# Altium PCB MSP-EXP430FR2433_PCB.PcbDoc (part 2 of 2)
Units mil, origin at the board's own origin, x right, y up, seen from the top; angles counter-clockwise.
Board outline 2300 x 2900 mil, 4 copper layers (Top Layer, VCC Layer, GND Layer, Bottom Layer), stack 30.634 mil thick; 130 components, 92 nets, 410 pads, 310 vias.
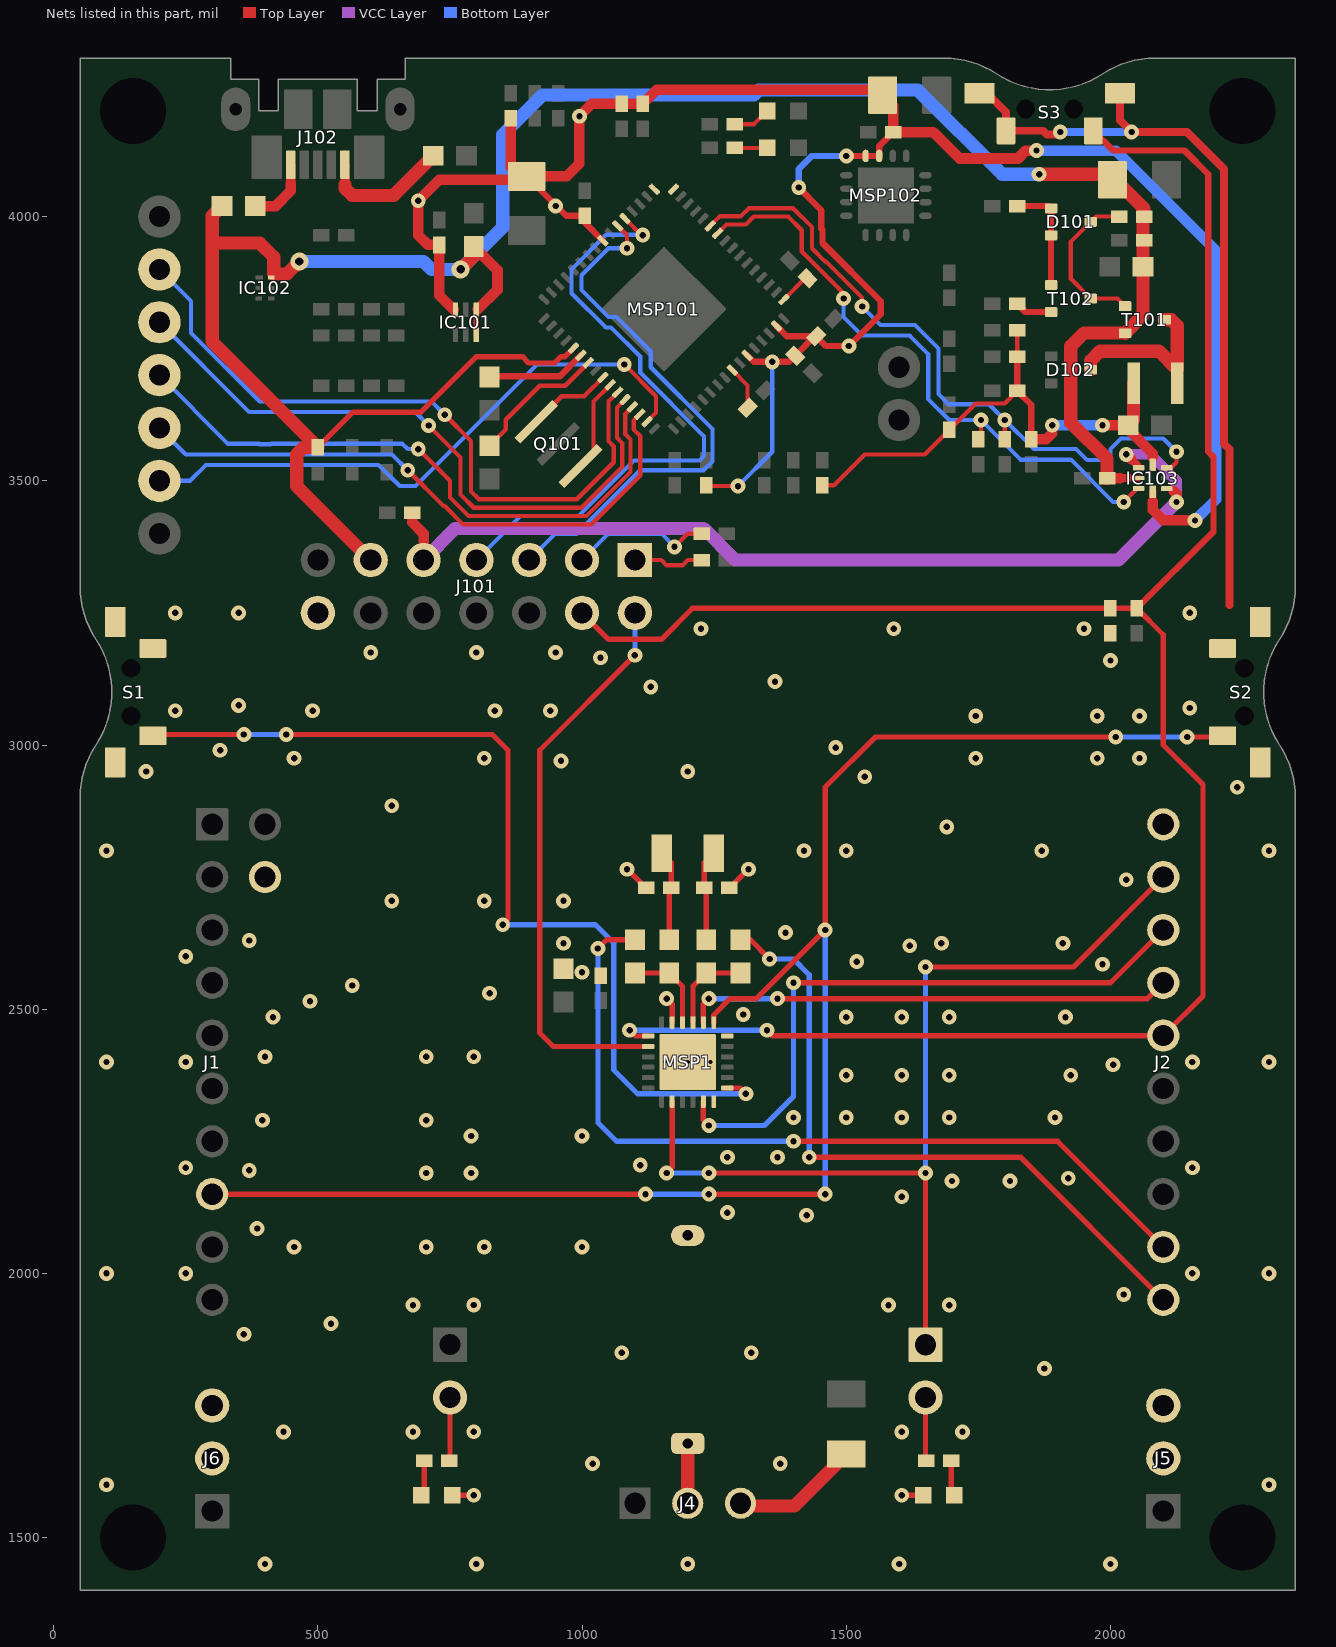
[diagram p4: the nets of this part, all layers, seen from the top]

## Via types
v1: diameter 28, hole 12, Top Layer to Bottom Layer, 304 vias
v2: diameter 19.68, hole 7.87, Top Layer to Bottom Layer, 3 vias
v3: diameter 34, hole 16, Top Layer to Bottom Layer, 2 vias
v4: diameter 32, hole 16, Top Layer to Bottom Layer, 1 vias

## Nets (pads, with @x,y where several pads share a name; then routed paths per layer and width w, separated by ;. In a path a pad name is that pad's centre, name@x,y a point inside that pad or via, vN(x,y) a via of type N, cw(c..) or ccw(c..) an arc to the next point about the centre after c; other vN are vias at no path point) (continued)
EZFET_TCK: MSP101.63 TP106.1 | length 1144.1
  Top Layer w8: v1(1080,3720) 1140,3660 1140,3629 MSP101.63@1123.01,3612.01
  Bottom Layer w8: TP106.1@200,3500 258,3500 288,3530 615,3530 655,3490 685,3490 915,3720 v1(1080,3720)
EZFET_TDI: MSP101.61 TP104.1 | length 1189
  Top Layer w8: v1(690,3560) 750,3500 750,3468.25 785,3433.25 1008.25,3433.25 1091.75,3516.75 1091.75,3578.25 1081.75,3588.25 1081.75,3626.44 MSP101.61@1095.16,3639.86
  Bottom Layer w8: TP104.1@200,3700 330,3570 388.41,3570 389.28,3569.13 410.72,3569.13 411.59,3570 660,3570 670,3560 v1(690,3560)
EZFET_TDO: MSP101.60 TP103.1 | length 1232.5
  Top Layer w8: v1(709.63,3604.63) 770,3544.27 770,3474.13 795,3449.13 999.13,3449.13 1075.87,3525.87 1075.87,3571.58 1065.87,3581.58 1065.87,3638.41 MSP101.60@1081.24,3653.78
  Bottom Layer w8: TP103.1@200,3800 370,3630 684.27,3630 v1(709.63,3604.63)
EZFET_TEST: MSP101.59 TP102.1 | length 1304
  Top Layer w8: v1(740,3625) 790,3575 790,3480 805,3465 990,3465 1060,3535 1060,3565 1050,3575 1050,3650.39 MSP101.59@1067.32,3667.7
  Bottom Layer w8: TP102.1@200,3900 260,3840 260,3780 390,3650 715,3650 v1(740,3625)
EZFET_TMS: MSP101.62 TP105.1 | length 1149.8
  Top Layer w8: v1(670,3520) 737.62,3452.38 740,3452.38 775,3417.38 1017.38,3417.38 1110,3510 1110,3585 1097.62,3597.38 1097.62,3614.47 MSP101.62@1109.09,3625.93
  Bottom Layer w8: TP105.1@200,3600 250,3550 640,3550 v1(670,3520)
EZFET_UARTCTS: MSP101.32
EZFET_UARTRTS: MSP101.33
EZFET_UARTRXD: J101.5 MSP101.38 | length 1044.5
  Top Layer w8: MSP101.38@1067.31,3982.29 1085,3964.6 v1(1085,3940)
  Bottom Layer w8: J101.5@900,3350 950,3400 990,3400 1110,3520 1230,3520 1246.81,3536.81 1246.81,3598.19 1130,3715 1130,3745 1065,3810 1050,3810 999.13,3860.87 999.13,3889.13 1050,3940 v1(1085,3940)
EZFET_UARTTXD: J101.7 MSP101.37 | length 1191.5
  Top Layer w8: MSP101.37@1081.23,3996.21 v1@1113.72,3963.72 ; v1(1115,3965) v1@1113.72,3963.72 ; v1@1113.72,3963.72 1112.44,3962.44 1115,3962.44 v1@1113.72,3963.72
  Bottom Layer w8: J101.7@800,3350 883.25,3433.25 993.25,3433.25 1098.62,3538.62 1221.97,3538.62 1230.87,3547.53 1230.87,3584.13 1110,3705 1110,3735 1055,3790 1045,3790 980,3855 980,3900 1045.87,3965.87 1114.13,3965.87 v1(1115,3965)
EZFET_V18: C102.2 MSP101.55 | length 262.5
  Top Layer w8: C102.2@825,3566.5 855.57,3597.07 855.57,3615.57 920,3680 968.23,3680 MSP101.55@1011.62,3723.39
EZFET_VBUS: C108.2 C109.1 C117.2 C118.2 C125.2 IC101.1 IC101.6 IC102.6 IC103.2 J101.11 L103.2 MSP101.53 R120.2 R124.1 T101.2 | length 4538.1
  Top Layer w10: R124.1@500,3563.62 566.38,3630 695,3630 800,3735 886.99,3735 898.87,3723.13 948.13,3723.13 960,3735 967.54,3735 MSP101.53@983.78,3751.24 ; IC101.6@799.68,3776.38 IC101.1@799.68,3824.41 ; 2035,3505 IC103.2@2053.43,3505
  Top Layer w15: 2018,3505 2035,3505
  Top Layer w20: C108.2@795,3943.5 840,3898.5 840,3861.61 IC101.1@802.8,3824.41 ; C125.2@1993.62,3505 2018,3505
  Top Layer w25: L103.2@318.5,4020 300,4001.5 300,3950 ; v3(465,3915) 441.37,3891.37 416.44,3891.37 416.44,3923.56 390,3950 300,3950 ; J101.11@600,3350 460,3490 460,3550 473.62,3563.62 R124.1@500,3563.62 300,3763.62 300,3950 ; v3(770,3900) 795,3925 C108.2@795,3943.5 ; v1(1865,4080) 1998.82,4080 2063.62,4015.2 R120.2@2063.62,4000 ; C125.2@1993.62,3505 1993.62,3541.38 1925,3610 1925,3755 1950,3780 T101.2@2027.01,3780 ; T101.2@2027.6,3779.41 2061.5,3813.31 C117.2@2061.5,3905 R120.2@2061.5,4002.13
  Bottom Layer w25: v3(465,3915) 700,3915 715,3900 v3(770,3900) 850,3980 850,4155 925,4230 1325,4230 1334.37,4239.37 1635.63,4239.37 1795,4080 v1(1865,4080)
EZFET_VCC: C103.2 C104.1 C105.2 C106.1 C113.2 C114.2 C124.2 IC101.3 IC103.4 MSP101.11 MSP101.15 MSP101.40 MSP102.15 MSP102.16 R109.1 R114.1 R116.1 R117.1 | length 4298.5
  Top Layer w8: R109.1@1236.38,3490 v1(1295,3490)
  Top Layer w12: C104.1@895,4076.18 969.8,4001.38 C103.2@1005,4001.38 ; C103.2@1005,3988.92 MSP101.40@1039.47,3954.45 ; MSP101.11@1312.29,3737.31 1324.6,3725 v1(1360,3725) 1391.59,3725 C114.2@1403.3,3736.7 C113.2@1439.89,3773.3 ; MSP101.15@1367.97,3792.99 1387.66,3773.3 C113.2@1439.89,3773.3 ; v1(1410,4055) 1452.87,4012.13 1452.87,3977.13 1455,3975 1455,3950 1565,3840 1565,3815 v1(1505,3755) 1461.59,3755 C113.2@1443.3,3773.3 C113.2@1439.89,3773.3 ; v1(1500.2,4114.8) MSP102.16@1536.61,4114.8 MSP102.15@1562.2,4114.8 1562.2,4133.58 C124.2@1588.62,4160
  Top Layer w15: 2080,3460 IC103.4@2080,3479.41
  Top Layer w20: IC101.3@757.2,3823.62 730,3850.83 C105.2@730,3946.38 708.62,3946.38 690,3965 v1(690,4030) 730,4070 C104.1@888.82,4070 ; R114.1@865,4186.38 865,4093.82 C104.1@888.82,4070 ; v1(1860,4125) 1840,4125 1825,4110 1715,4110 1665,4160 C124.2@1588.62,4160 1588.62,4210.2 C106.1@1568.82,4230 1558.82,4240 1141.38,4240 R116.1@1115,4213.62 R117.1@1075,4213.62 1018.62,4213.62 v1(995,4190) 995,4100 971.18,4076.18 C104.1@895,4076.18 C104.1@888.82,4070 ; 2080,3460 2080,3445 2100,3425 v1(2160,3425)
  Bottom Layer w8: v1(1295,3490) 1360,3555 v1(1360,3725)
  Bottom Layer w12: v1(1410,4055) 1410,4090 1434.8,4114.8 v1(1500.2,4114.8)
  Bottom Layer w20: v1(1860,4125) 2010,4125 2200,3935 2200,3465 v1(2160,3425)
  other v1: 950,4020
EZFET_VCCEN1: IC103.3 MSP101.26 R107.2 | length 1182.1
  Top Layer w8: MSP101.26@1256.61,3968.38 1273.23,3985 1310,3985 1325,4000 1390,4000 1415.87,3974.13 1415.87,3934.13 1495,3855 v1(1495,3845) ; R107.2@1750,3578.62 1755,3583.62 v1(1755,3615) ; v1(2025,3460) 2050,3485 2053.11,3485 IC103.3@2053.43,3485.31
  Bottom Layer w8: v1(1495,3845) 1495,3810 1530,3775 1620,3775 1655,3740 1655,3655 1695,3615 v1(1755,3615) 1830,3540 1925,3540 2005,3460 v1(2025,3460)
EZFET_VCCEN2: IC103.7 MSP101.27 R108.2 | length 1289.7
  Top Layer w8: MSP101.27@1242.68,3982.3 1261.26,4000.87 1300.87,4000.87 1315.87,4015.87 1399.13,4015.87 1435,3980 1435,3940 1460,3915 1461.59,3915 1530,3846.59 v1(1530,3830) ; R108.2@1800,3578.62 v1(1800,3615) ; IC103.7@2106.57,3524.69 2114.68,3524.69 2125,3535 v1(2125,3555)
  Bottom Layer w8: v1(1530,3830) 1565,3795 1630,3795 1674.5,3750.5 1674.5,3664.12 1693.62,3645 1770,3645 v1(1800,3615) 1855,3560 1935,3560 1955.87,3539.13 1989.13,3539.13 2000,3550 2000,3560 2020,3580 2100,3580 v1(2125,3555)
EZFET_VCCOUT: C119.2 C120.2 IC103.8 L101.2 R112.1 R121.1 R126.2 R127.2 R128.1 | length 1041
  Top Layer w8: R121.1@1455,3491.38 1476.38,3491.38 1535,3550 1648.62,3550 R112.1@1695,3596.38 1744.94,3646.31 1799.94,3646.31 R127.2@1823.62,3670 ; R128.1@1823.62,3735 R126.2@1823.62,3785
  Top Layer w10: IC103.8@2080,3530.59 2080,3545
  Top Layer w12: R128.1@1823.62,3735 R127.2@1823.62,3670 1850,3643.62 C120.2@1850,3578.62
  Top Layer w20: C120.2@1850,3578.62 1878.62,3578.62 1890,3590 v1(1890,3605) ; v1(1985,3605) C119.2@2033.5,3605 2033.5,3597.95 2080,3551.46 2080,3545
  Top Layer w25: C119.2@2033.5,3605 2043.66,3615.16 L101.2@2043.66,3685
  Bottom Layer w20: v1(1890,3605) v1(1985,3605)
EZFET_VCCTARGET: C127.1 IC103.1 IC103.5 J101.9 | length 1845.7
  Top Layer w8: IC103.5@2106.57,3485.31 IC103.5@2114.68,3485.31
  Top Layer w12: 2050,3530 IC103.1@2053.43,3526.57 ; IC103.5@2114.68,3485.31 2120,3480
  Top Layer w15: v1@2038.58,3541.42 2050,3530
  Top Layer w20: C127.1@678.62,3440 678.62,3421.38 700,3400 J101.9@700,3350 ; v1(2030,3550) v1@2038.58,3541.42 ; 2120,3480 2125,3475 v1(2125,3460)
  VCC Layer w20: v1(2030,3550) 2075,3550 2125,3500 v1(2125,3460)
  VCC Layer w25: J101.9@700,3350 760,3410 1230,3410 1290,3350 2015,3350 v1(2125,3460)
EZFET_VREF: C121.2 MSP101.9 | length 83.1
  Top Layer w8: MSP101.9@1284.45,3709.47 1313.3,3680.62 C121.2@1313.3,3638.3
EZFET_VUSB: C107.2 MSP101.54 | length 189.6
  Top Layer w12: C107.2@825,3696.5 826.38,3697.87 958.26,3697.87 MSP101.54@997.7,3737.32
GND: C1.2 C2.2 C3.2 C4.2 C5.1 C6.2 J2.20 J3.22 J5.2 J5.3 J6.2 J6.3 J101.14 LED1.2 LED2.2 MSP1.18 MSP1.23 MSP1.25@1200,2400 S1.1 S1.2 S1.3 S2.1 S2.2 S2.4 S3.1 S3.2 S3.4 | length 1688.8
  Top Layer w10: LED1.2@754.53,1580.14 v1(795,1580.14) ; v1(1085,2765) 1120,2730 C3.2@1121.38,2730 ; v1(1160,2520) 1170.47,2509.53 MSP1.23@1170.47,2474.8 ; C2.2@1278.62,2730 1280,2730 v1(1315,2765) ; v1(1605,1580) LED2.2@1645.47,1580
  Top Layer w15: S3.2@1752.13,4233.31 1766.69,4233.31 1802.32,4197.68 S3.4@1802.32,4162.44 1872.56,4162.44 1880,4155 v1@1905,4155 ; S3.1@2017.87,4233.31 2017.87,4182.13 v1(2040,4160) 2145,4160 2215,4090 2215,3570 2225,3560 2225,3265
  Bottom Layer w15: v1(1905,4160) v1(2040,4160)
  other v1: 400,1450 800,1450 1200,1450 1600,1450 2000,1450 100,1600 2300,1600 1020,1640 1375,1640 435,1700 680,1700 795,1700.14 1605,1700 1720,1700 1875,1820 1075,1850 1320,1850 360,1885 525,1905 680,1940 795,1940.14 1580,1940 1695,1940 2025,1960 100,2000 250,2000 2155,2000 2300,2000 455,2050 705,2050 815,2050 1000,2050 385,2085 1425,2110 1275,2115 1605,2145 1700,2175 1810,2175 1920,2180 705,2190 790,2190 370,2195 250,2200 2155,2200 1110,2205 1275,2220 1370,2220 790,2260 1000,2260 395,2290 705,2290 1400,2295 1500,2295 1605,2295 1695,2295 1895,2295 1500,2375 1605,2375 1695,2375 1925,2375 2005,2395 100,2400 250,2400 2155,2400 2300,2400 400,2410 705,2410 795,2410 415,2485 1500,2485 1605,2485 1695,2485 1915,2485 1305,2490 485,2515 825,2530 565,2545 1000,2570 1985,2585 1520,2590 250,2600 1620,2620 965,2625 1680,2625 1910,2625 370,2630 1385,2645 640,2705 815,2705 965,2705 2030,2745 100,2800 1420,2800 1500,2800 1870,2800 2300,2800 1690,2845 640,2885 2240,2920 1535,2940 175,2950 1200,2950 960,2970 455,2975 815,2975 1745,2975 1975,2975 2055,2975 315,2990 1480,2995 1745,3055 1975,3055 2055,3055 230,3065 490,3065 835,3065 940,3065 2150,3070 350,3075 1130,3110 1365,3120 2000,3160 1035,3165 600,3175 800,3175 950,3175 1225,3220 1590,3220 1950,3220 230,3250 350,3250 2150,3250
  other v2: 1156.69,2400 1200,2400 1243.31,2400
LED2: J2.19 J11.1 MSP1.8 | length 1865
  Top Layer w10: v1(1160,2190) 1170.47,2200.47 MSP1.8@1170.47,2325.2 ; v1(1240,2190) v1(1650,2190) J11.1@1650,1865 ; v1(1650,2580) 1930,2580 J2.19@2100,2750
  Bottom Layer w10: v1(1160,2190) v1(1240,2190) ; v1(1650,2190) v1(1650,2580)
NetC6_1: C6.1 J4.2 | length 117.1
  Top Layer w25: J4.2@1200,1565 C6.1@1200,1682.15
NetC101_2: C101.2 MSP101.17 | length 61.5
  Top Layer w8: MSP101.17@1381.91,3843.07 1422.14,3883.3 C101.2@1426.7,3883.3
NetD101_1: D101.1 D101.2 R118.1 T102.1 | length 210.8
  Top Layer w12: R118.1@1823.62,4020 1883.19,4020 D101.1@1887.6,4015.59 T102.1@1887.6,3870.59
NetD101_3: D101.3 R120.1 T101.1 T102.3 | length 305.3
  Top Layer w8: R120.1@2016.38,4000 1972.4,4000 D101.3@1962.4,3990 1925,3952.6 1925,3882.4 T102.3@1962.4,3845 2013.19,3845 T101.1@2027.6,3830.59
NetD102_3: D102.3 L101.1 T101.3 | length 314.6
  Top Layer w25: D102.3@1962.4,3710 1962.4,3727.4 1980,3745 2091.93,3745 2126.34,3710.59 2126.34,3793.66 2115,3805 T101.3@2102.4,3805
NetJ4_3: J4.3 R8.2 | length 240.6
  Top Layer w25: J4.3@1300,1560 1402.09,1560 R8.2@1500,1657.91
NetJ10_2: J10.2 R6.2 | length 120.6
  Top Layer w10: R6.2@748.62,1645.14 750,1646.51 J10.2@750,1765.14
NetJ11_2: J11.2 R7.2 | length 120.6
  Top Layer w10: J11.2@1650,1765 1650,1646.38 R7.2@1651.38,1645
NetJ101_1: J101.1 R129.2 | length 134.7
  Top Layer w8: J101.1@1100,3350 1150,3350 1160,3340 1190,3340 1200,3350 R129.2@1226.38,3350
NetJ101_3: J101.3 R130.2 | length 267.8
  Top Layer w8: v1(1175,3375) 1200,3400 R130.2@1226.38,3400
  Bottom Layer w8: J101.3@1000,3350 1050,3400 1150,3400 v1(1175,3375)
NetJ102_1: J102.1 L103.1 | length 128.6
  Top Layer w17.5: 448.79,4065.06 J102.1@448.82,4098.19
  Top Layer w18: 448.79,4063.64 448.79,4065.06
  Top Layer w20: L103.1@381.5,4020 420,4020 448.79,4048.79 448.79,4063.64
NetJ102_5: J102.5 L102.1 | length 243.2
  Top Layer w17.5: 551.18,4065.39 J102.5@551.18,4098.19
  Top Layer w25: 551.21,4060.11 551.21,4053.79 565,4040 643.5,4040 L102.1@718.5,4115
NetLED1_1: LED1.1 R6.1 | length 67.4
  Top Layer w10: LED1.1@695.47,1580.14 701.38,1586.04 R6.1@701.38,1645.14
NetLED2_1: LED2.1 R7.1 | length 67.4
  Top Layer w10: R7.1@1698.62,1645 1698.62,1585.91 LED2.1@1704.53,1580
NetLED101_1: LED101.1 R101.1 | length 61.9
  Top Layer w8: R101.1@1288.62,4130 LED101.1@1350.47,4130
NetLED102_1: LED102.1 R102.1 | length 72.2
  Top Layer w8: R102.1@1288.62,4175 1325.47,4175 LED102.1@1350.47,4200
NetMSP101_57: MSP101.57 Q101.1 | length 160.9
  Top Layer w8: Q101.1@913.24,3611.76 961.48,3660 1003.92,3660 MSP101.57@1039.47,3695.55
NetMSP101_58: MSP101.58 Q101.3 | length 176.8
  Top Layer w8: Q101.3@996.76,3528.24 1021.81,3553.3 1021.81,3650.04 MSP101.58@1053.39,3681.62
NetR119_2: R119.2 T102.2 | length 70.4
  Top Layer w12: R119.2@1823.62,3835 1839.21,3819.41 T102.2@1887.6,3819.41
P2.0: MSP1.21 R2.2 R4.2 | length 169.1
  Top Layer w10: MSP1.21@1209.84,2474.8 1209.84,2543.35 R2.2@1235,2568.5 R4.2@1300,2568.5
P2.0_BP: J2.11 R4.1 | length 1284.4
  Top Layer w10: R4.1@1300,2631.5 1318.5,2631.5 v1(1355,2595) ; v1(1430,2220) 1830,2220 J2.11@2100,1950
  Bottom Layer w10: v1(1355,2595) 1400,2595 1430,2565 v1(1430,2220)
P2.1: MSP1.22 R3.2 R5.2 | length 169.1
  Top Layer w10: R5.2@1100,2568.5 R3.2@1165,2568.5 1190.16,2543.35 MSP1.22@1190.16,2474.8
P2.1_BP: J2.12 R5.1 | length 1574.2
  Top Layer w10: v1(1030,2615) 1046.5,2631.5 R5.1@1100,2631.5 ; v1(1400,2250) 1900,2250 J2.12@2100,2050
  Bottom Layer w10: v1(1030,2615) 1030,2285 1065,2250 v1(1400,2250)
P2.2: J2.18 MSP1.11 | length 1188.7
  Top Layer w10: MSP1.11@1229.53,2325.2 1229.53,2290.47 v1(1240,2280) ; v1(1400,2550) 2000,2550 J2.18@2100,2650
  Bottom Layer w10: v1(1240,2280) 1345,2280 1400,2335 v1(1400,2550)
P2.3: MSP1.13 S1.4 | length 1792.9
  Top Layer w10: S1.4@187.56,3017.32 190.24,3020 v1(360,3020) ; v1(440,3020) 830,3020 860,2990 860,2670 v1(850,2660) ; MSP1.13@1274.8,2350.79 1299.21,2350.79 v1(1310,2340)
  Bottom Layer w10: v1(360,3020) v1(440,3020) ; v1(850,2660) 1025,2660 1060,2625 1060,2385 1105,2340 v1(1310,2340)
P2.7: J1.8 MSP1.19 S2.3 | length 3014.5
  Top Layer w10: J1.8@300,2150 v1(1120,2150) ; v1(1240,2150) v1(1460,2150) ; MSP1.19@1249.21,2474.8 1249.21,2489.21 1280,2520 1330,2520 v1(1460,2650) 1460,2920 1555,3015 v1(2010,3015) ; v1(2145,3015) 2210.12,3015 S2.3@2212.44,3017.32
  Bottom Layer w10: v1(1120,2150) v1(1240,2150) ; v1(1460,2150) v1(1460,2650) ; v1(2010,3015) v1(2145,3015)
P3.0: MSP1.12
P3.2: J2.17 MSP1.20 | length 922
  Top Layer w10: MSP1.20@1229.53,2474.8 1229.53,2509.53 v1(1240,2520) ; v1(1370,2520) 2070,2520 J2.17@2100,2550
  Bottom Layer w10: v1(1240,2520) v1(1370,2520)
R\S\T\: C1.1 J2.16 J101.4 MSP1.1 R1.1 S3.3 | length 4177.3
  Top Layer w10: J101.4@1000,3250 1050,3200 1150,3200 1208.62,3258.62 C1.1@2000,3258.62 R1.1@2050,3258.62 2100,3208.62 2100,3000 2175,2925 2175,2525 J2.16@2100,2450 1360,2450 v1(1350,2460) ; v1(1090,2460) 1100.79,2449.21 MSP1.1@1125.2,2449.21
  Top Layer w12: S3.3@1967.68,4162.44 2005.12,4125 2140,4125 2185,4080 2185,3555 2195,3545 2195,3403.62 R1.1@2050,3258.62
  Bottom Layer w10: v1(1090,2460) v1(1350,2460)
SBWTCK: J101.2 MSP1.2 | length 1090.3
  Top Layer w10: v1@1100,3175 v1(1100,3170) 920,2990 920,2455 945.47,2429.53 MSP1.2@1125.2,2429.53
  Bottom Layer w10: v1(1100,3170) J101.2@1100,3250
XIN: C3.1 Q1.1 R3.1 | length 172.4
  Top Layer w10: Q1.1@1150.79,2795 1168.62,2777.17 C3.1@1168.62,2730 1165,2726.38 R3.1@1165,2631.5
XOUT: C2.1 Q1.2 R2.1 | length 172.4
  Top Layer w10: R2.1@1235,2631.5 1235,2726.38 C2.1@1231.38,2730 1231.38,2777.17 Q1.2@1249.21,2795
pads on no net: IC101.4 IC101.5 IC102.2 J102.4 MH1.1 MH2.1 MH3.1 MH4.1 MSP1.25@1172.64,2372.64 MSP1.25@1172.64,2427.36 MSP1.25@1227.36,2372.64 MSP1.25@1227.36,2427.36 MSP101.3 MSP101.4 MSP101.10 MSP101.12 MSP101.13 MSP101.18 MSP101.19 MSP101.22 MSP101.23 MSP101.24 MSP101.25 MSP101.29 MSP101.30 MSP101.31 MSP101.36 MSP101.41 MSP101.42 MSP101.46 MSP101.47 MSP101.48 MSP101.65@1077.61,3825 MSP101.65@1116.3,3786.3 MSP101.65@1116.3,3863.7 MSP101.65@1155,3747.61 MSP101.65@1155,3825 MSP101.65@1155,3902.39 MSP101.65@1193.7,3786.3 MSP101.65@1193.7,3863.7 MSP101.65@1232.39,3825 S1. S2. S3. SH-J4.0 SH-J10.0 SH-J11.0 SH-J101-1.0 SH-J101-2.0 SH-J101-3.0 SH-J101-4.0 SH-J101-5.0 SH-J101-6.0 SH-J101-7.0
copper on no net:
  other v1: 890,3890 955,3955

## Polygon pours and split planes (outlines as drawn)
EZ_GND on GND Layer "EZ_GND-GND" (solid, remove dead copper, pour order 5): 50,4300 2350,4300 2350,3310 50,3310
GND on GND Layer "GND-GND" (solid, remove dead copper, pour order 16): 50,3290 2350,3290 2350,1400 50,1400
EZ_GND on Bottom Layer "EZ_GND-BOT" (solid, remove dead copper, pour order 8): 50,4300 2350,4300 2350,3310 50,3310
GND on Bottom Layer "GND-BOTTOM" (solid, remove dead copper, pour order 19): 50,3290 2350,3290 2350,1400 50,1400
EZFET_VCC on VCC Layer "EZFET_VCC-VCC" (solid, remove dead copper, pour order 10): 50,4300 2350,4300 2350,3310 50,3310
3V3 on VCC Layer "3V3-VCC" (solid, remove dead copper, pour order 18): 50,3290 2350,3290 2350,1400 50,1400
EZ_GND on Top Layer "EZ_GND_USB_CONNECTION" (solid, remove dead copper, pour order 12): 695,4280 695,4150 750,4095 840,4095 840,4280
GND on Top Layer "GND-TOP" (solid, remove dead copper, pour order 14): 50,3290 2350,3290 2350,1400 50,1400
3V3 on Top Layer "TOP_LAYER_3V3_P019" (solid, remove dead copper, pour order 4): 1425,1745 1425,1915 1575,1915 1575,1745

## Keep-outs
Keep-Out Layer:
  text ".Layer_Name" at 577,-858.49 h60

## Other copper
Top Layer:
  pour cut-out: 1030,3730 1075,3685 1075,3680 1050,3655 1050,3550 970,3470 850,3590 940,3680 980,3680
  pour cut-out: 1180,2460 1220,2460 1220,2530 1230,2540 1325,2540 1330,2545 1330,2660 1310,2680 1310,2745 1285,2770 1285,2840 1280,2845 1120,2845 1115,2840 1115,2770 1090,2745 1090,2680 1070,2660 1070,2545 1075,2540 1170,2540 1180,2530
  text ".Layer_Name" at 577,-858.49 h60
VCC Layer:
  pour cut-out: 1030,3730 1075,3685 1075,3680 1050,3655 1050,3550 970,3470 850,3590 940,3680 980,3680
  pour cut-out: 1180,2460 1220,2460 1220,2530 1230,2540 1325,2540 1330,2545 1330,2660 1310,2680 1310,2745 1285,2770 1285,2840 1280,2845 1120,2845 1115,2840 1115,2770 1090,2745 1090,2680 1070,2660 1070,2545 1075,2540 1170,2540 1180,2530
GND Layer:
  pour cut-out: 1030,3730 1075,3685 1075,3680 1050,3655 1050,3550 970,3470 850,3590 940,3680 980,3680
  pour cut-out: 1180,2460 1220,2460 1220,2530 1230,2540 1325,2540 1330,2545 1330,2660 1310,2680 1310,2745 1285,2770 1285,2840 1280,2845 1120,2845 1115,2840 1115,2770 1090,2745 1090,2680 1070,2660 1070,2545 1075,2540 1170,2540 1180,2530
Bottom Layer:
  pour cut-out: 1030,3730 1075,3685 1075,3680 1050,3655 1050,3550 970,3470 850,3590 940,3680 980,3680
  pour cut-out: 1180,2460 1220,2460 1220,2530 1230,2540 1325,2540 1330,2545 1330,2660 1310,2680 1310,2745 1285,2770 1285,2840 1280,2845 1120,2845 1115,2840 1115,2770 1090,2745 1090,2680 1070,2660 1070,2545 1075,2540 1170,2540 1180,2530
  text ".Layer_Name" at 577,-858.49 h60

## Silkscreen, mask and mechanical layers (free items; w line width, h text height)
Top Overlay:
  rectangle: 1470,2615 1495,2665
  rectangle: 1575,2615 1600,2665
  rectangle: 1770,2615 1795,2665
  rectangle: 1735,2615 1760,2665
  lines w5: 1650,2520 1650,2715 ; 1420,2520 1880,2520 1880,2715 1420,2715 1420,2520 ; 1470,2615 1495,2615 1495,2665 1470,2665 1470,2615 ; 1505,2615 1530,2615 1530,2665 1505,2665 1505,2615 ; 1540,2615 1540,2665 1565,2665 1565,2615 1540,2615 ; 1575,2615 1600,2615 1600,2665 1575,2665 1575,2615 ; 1700,2615 1700,2665 1725,2665 1725,2615 1700,2615 ; 1735,2615 1735,2665 1760,2665 1760,2615 1735,2615 ; 1770,2615 1795,2615 1795,2665 1770,2665 1770,2615 ; 1805,2615 1805,2665 1830,2665 1830,2615 1805,2615
  lines w8: 1200,1450 1200,1465 ; 1200,1475 1200,1490 ; 1200,1500 1200,1515
  lines w10: 50,3300 150,3300 ; 250,3300 350,3300 ; 450,3300 550,3300 ; 650,3300 750,3300 ; 850,3300 950,3300 ; 1050,3300 1150,3300 ; 1250,3300 1350,3300 ; 1450,3300 1550,3300 ; 1650,3300 1750,3300 ; 1850,3300 1950,3300 ; 2050,3300 2150,3300 ; 2250,3300 2350,3300
  text "MSP RST" at 1715,4095 h40
  text "eZ-FET Debug Probe" at 1315,3330 h40
  text "Rev1.4" at 2045,3330 h30
  text "MSP-EXP430FR2433" at 2280,3320 h50 r90
  text "Rev .PCB_Rev" at 2334.71,3319.67 h30 r90
  text "P2.3" at 215,3080 h40
  text "P2.7" at 2045,3080 h40
  text "Crystal" at 1555,2810 h30
  text "Selection" at 1525,2770 h30
  text "P1.0" at 95,2730 h40
  text "Resistors" at 1525,2730 h30
  text "P1.1" at 2165,2730 h40
  text "R5" at 1465,2675 h20
  text "R4" at 1570,2675 h20
  text "R3" at 1725,2675 h20
  text "R2" at 1770,2675 h20
  text "P1.5" at 95,2630 h40
  text "P2.2" at 2165,2630 h40
  text "P2.1" at 1440,2585 h20
  text "P2.0" at 1560,2585 h20
  text "XIN" at 1705,2585 h20
  text "XOUT" at 1775,2585 h20
  text "J2 Pins" at 1435,2540 h30
  text "Crystal" at 1670,2540 h30
  text "P1.4" at 95,2530 h40
  text "P3.2" at 2165,2530 h40
  text "(Default)" at 1420,2475 h30
  text "P1.6" at 95,2430 h40
  text "RST" at 2165,2430 h40
  text "P1.7" at 95,2330 h40
  text "P2.6" at 2165,2330 h40
  text "MSP430FR2433" at 965,2255 h40
  text "P2.4" at 95,2230 h40
  text "P2.5" at 2165,2230 h40
  text "P2.7" at 95,2130 h40
  text "P3.1" at 2165,2130 h40
  text "Super" at 980,2085 h30
  text "Cap" at 1295,2085 h30
  text "P1.3" at 95,2030 h40
  text "P2.1" at 2165,2030 h40
  text "P1.2" at 95,1930 h40
  text "P1.0" at 720,1930.14 h40 r45
  text "P1.1" at 1620,1930 h40 r45
  text "P2.0" at 2165,1930 h40
  text "DNP" at 1160,1865 h30
  text "1" at 1020,1520 h30
  text "3" at 1370,1520 h30
  text "Use" at 1075,1465 h30
  text "Charge" at 1225,1465 h30
  text ".Layer_Name" at 577,-858.49 h60
Bottom Overlay:
  drawing of 4643 lines, arcs and shapes, not listed
  text "P1.0" at 235,2730 h40
  text "P1.1" at 2305,2730 h40
  text "P1.5" at 235,2630 h40
  text "P2.2" at 2305,2630 h40
  text "P1.4" at 235,2530 h40
  text "P3.2" at 2305,2530 h40
  text "P1.6" at 235,2430 h40
  text "RST" at 2275,2430 h40
  text "P1.7" at 235,2330 h40
  text "P2.6" at 2305,2330 h40
  text "P2.4" at 235,2230 h40
  text "P2.5" at 2305,2230 h40
  text "P2.7" at 235,2130 h40
  text "P3.1" at 2305,2130 h40
  text "P1.3" at 235,2030 h40
  text "P2.1" at 2305,2030 h40
  text "P1.2" at 235,1930 h40
  text "P2.0" at 2305,1930 h40
  text "'.PRJ_Number'" at 495,1430 h40
  text ".Layer_Name" at 577,-858.49 h60
Top Paste:
  text ".Layer_Name" at 577,-858.49 h60
Bottom Paste:
  text ".Layer_Name" at 577,-858.49 h60
Top Solder:
  text ".Layer_Name" at 577,-858.49 h60
  text ".Layer_Name" at 577,-858.49 h60
Bottom Solder:
  text ".Layer_Name" at 577,-858.49 h60
Drill Guide:
  text ".Layer_Name" at 577,-858.49 h60
M1 Board Outline:
  the board outline again, w10
  text ".Layer_Name" at 577,-858.49 h60
M2 Board Dimensions:
  rectangle: 0,-275 125,-150
  rectangle: 125,-400 500,-275
  lines w7: 0,-275 1000,-275 ; 125,-400 125,-150 ; 250,-400 250,-150 ; 500,-400 500,-150 ; 750,-400 750,-150 ; 0,-400 1000,-400 1000,-150 0,-150 0,-400
  text ".Layer_Name" at 577,-858.49 h60
M3 3D STEP Top:
  text ".Layer_Name" at 577,-858.49 h60
M4 3D STEP Bottom:
  text ".Layer_Name" at 577,-858.49 h60
M5 Assembly Top:
  lines w10: -292,-930.17 6308,-930.17 ; -292,-726.83 6310,-726.83 ; -292,-523.5 -292,-1133.5 3713,-1133.5 6310,-1133.5 6310,-523.5 -291.5,-523.5 -291.5,-1133.5 1284,-1133.5 ; 2173,-1133.5 2173,-523.5 ; 3440,-726.83 3440,-523.5 ; 4280,-726.83 4280,-523.5 ; 4902,-1140 4902,-937.17
  text "COMPONENTS MARKED 'DNP' SHOULD NOT BE POPULATED." at 1153.5,-318.5 h60
  text "ASSEMBLY VARIANT:" at 1153,-434 h60
  text ".VariantName" at 2189,-434 h60
  text "PCB VIEWED FROM TOP SIDE" at -228.5,-655.67 h60
  text "BOARD #:" at 2248,-655.67 h60
  text ".PRJ_Number" at 2793.5,-655.67 h60
  text "REV:" at 3638,-655.67 h60
  text ".PCB_Rev" at 3929.5,-655.67 h60
  text "SVN REV:" at 4476,-655.67 h60
  text ".VersionControl_RevNumber" at 4982,-655.67 h60
  text "TID #:" at 2248,-859 h60
  text ".TID" at 2793.5,-859 h60
  text "PLOT NAME =" at -228.5,-1064.34 h60
  text ".plot_File_Name" at 577,-1064.34 h60
  text "GENERATED    :" at 2250,-1064.34 h60
  text ".Print_Date" at 3119.5,-1064.34 h60
  text ".Print_Time" at 3848.5,-1064.34 h60
  text "TEXAS INSTRUMENTS" at 5113,-1064.34 h60
M6 Assembly Bottom:
  lines w10: -292.5,-727.33 6309.5,-727.33 ; -290.5,-930.67 6309.5,-930.67 ; 1115.5,-1140.5 1115.5,-937.67 ; 1737.5,-727.33 1737.5,-524 ; 2577.5,-727.33 2577.5,-524 ; 3844.5,-1134 3844.5,-524 ; 4733.5,-1134 6309,-1134 6309,-524 -292.5,-524 -292.5,-1134 2304.5,-1134 6309.5,-1134 6309.5,-524
  text "COMPONENTS MARKED 'DNP' SHOULD NOT BE POPULATED." at 6102,-318 h60
  text ".VariantName" at 5058,-434 h60
  text "ASSEMBLY VARIANT:" at 6097,-434 h60
  text ".VersionControl_RevNumber" at 1035.5,-656.17 h60
  text "SVN REV:" at 1541.5,-656.17 h60
  text ".PCB_Rev" at 2088,-656.17 h60
  text "REV:" at 2379.5,-656.17 h60
  text ".PRJ_Number" at 3224,-656.17 h60
  text "BOARD #:" at 3769.5,-656.17 h60
  text "PCB VIEWED FROM BOTTOM SIDE" at 6246,-656.17 h60
  text ".TID" at 3224,-859.5 h60
  text "TID #:" at 3769.5,-859.5 h60
  text "TEXAS INSTRUMENTS" at 904.5,-1064.84 h60
  text ".Print_Time" at 2169,-1064.84 h60
  text ".Print_Date" at 2898,-1064.84 h60
  text "GENERATED    :" at 3767.5,-1064.84 h60
  text ".plot_File_Name" at 5440.5,-1064.84 h60
  text "PLOT NAME =" at 6246,-1064.84 h60
M9 Title Sheet:
  drawing of 57 lines, arcs and shapes, not listed
  text "1" at 739.84,8036.5 h70
  text "2" at 3235.5,8036.5 h70
  text "3" at 5724.84,8036.5 h70
  text "4" at 8231.51,8036.5 h70
  text "5" at 10730.5,8036.5 h70
  text "6" at 13235.5,8036.5 h70
  text "A" at -416.5,6893.5 h70
  text "A" at 14383.5,6893.5 h70
  text "B" at -416.5,4513.5 h70
  text "B" at 14383.5,4513.5 h70
  text "C" at -416.5,2138.5 h70
  text "C" at 14383.5,2138.5 h70
  text "PROJECT TITLE:" at 11343.5,277.5 h45
  text ".PRJ_Title" at 11393.5,144.17 h70
  text "DESIGNED FOR:" at 11343.5,-23.5 h45
  text ".PRJ_Customer" at 11393.5,-163.5 h70
  text "D" at -416.5,-231.5 h70
  text "D" at 14383.5,-231.5 h70
  text "FILE NAME:" at 11343.5,-323.5 h45
  text ".PCB_File_Name_No_Path" at 11393.5,-443.5 h70
  text "Texas Instruments (TI) and/or its licensors do not warrant the accuracy or completeness of this specification" at 6374,-605.34 h45
  text "ENGINEER:" at 11343.5,-613.5 h45
  text "LAYOUT BY:" at 12848.5,-613.5 h45
  text "or any information contained therein. TI and/or its licensors do not warrant that this design will meet" at 6329.01,-718 h45
  text ".PRJ_Engineer" at 11393.5,-768.49 h70
  text ".PCB_Layout" at 12899,-768.49 h70
  text "the specifications, will be suitable for your application or fit for any particular purpose, or will operate in" at 6329.01,-830.67 h45
  text ".Layer_Name" at 577,-858.49 h60
  text "ALTIUM DESIGNER VERSION:" at 12848.5,-923.5 h45
  text "an implementation. TI and/or its licensors do not warrant that the design is production worthy. You should" at 6329.01,-943.33 h45
  text "completely validate and test your design implementation to confirm the system functionality for your application." at 6374,-1056 h45
  text ".print_Scale" at 11393.5,-1056.83 h70
  text ".Application_BuildNumber" at 12899,-1056.83 h70
  text "1" at 739.84,-1263.5 h70
  text "2" at 3235.5,-1263.5 h70
  text "3" at 5724.84,-1263.5 h70
  text "4" at 8231.51,-1263.5 h70
  text "5" at 10730.5,-1263.5 h70
  text "6" at 13235.5,-1263.5 h70
M10 Fab Notes:
  drawing of 173 lines, arcs and shapes, not listed
  text "DESIGN INFORMATION" at 12378.02,6201 h60
  text "MIN. TRACK WIDTH:" at 11733.46,6021 h60
  text "8" at 12829.7,6021 h60
  text "MIL" at 12984.46,6021 h60
  text "MIN. CLEARANCE:" at 11733.46,5889 h60
  text "0.2" at 12769.7,5889 h60
  text "mm" at 12984.46,5889 h60
  text "MIN. VIA PAD SIZE:" at 11733.46,5757 h60
  text "24" at 12799.71,5757 h60
  text "MIL" at 12984.46,5757 h60
  text "0.05mm (2MIL)" at 12428.46,5615.29 h60
  text "MINIMUM ANNULAR RING" at 11404.23,5611 h60
  text "EXTERNAL" at 13136.46,5611 h60
  text "PER" at 11604.23,5493 h60
  text "IPC-D-275 CLASS 2 LEVEL C" at 11824.23,5493 h60
  text "MIL, HOLES" at 13312.46,5380.71 h60
  text "+/-" at 12920,5380 h60
  text "+/-" at 13774,5380 h60
  text "REGISTRATION TOLERANCES:" at 11404.23,5375 h60
  text "METAL" at 12604,5375 h60
  text "5" at 13180.2,5375 h60
  text "3" at 14013.2,5375 h60
  text "MIL" at 14129.46,5375 h60
  text "+/-" at 13774,5262 h60
  text "HOLE SIZE TOLERANCE (UNLESS OTHERWISE SPECIFIED):" at 11404.23,5257 h60
  text "3" at 14013.2,5257 h60
  text "MIL" at 14129.46,5257 h60
  text "MATERIAL:" at 11329.46,5047.54 h60
  text "FR-4 High Tg" at 12315.9,4907.21 h60
  text "FR-408" at 11750.46,4898.64 h60
  text "OTHER" at 13238.46,4898.64 h60
  text "X" at 12161,4895 h60
  text "62 MIL (1.6mm) +/-10%" at 12070.56,4735.92 h60
  text "THICKNESS:" at 11404.23,4731.64 h60
  text "X" at 11942.4,4731.64 h60
  text "OTHER" at 13355.46,4731.64 h60
  text "TOLERANCE:" at 11404.23,4573.64 h60
  text "X" at 12243.53,4573.64 h60
  text "ANSI IPC-6012 TYPE 3 CLASS 2" at 12430.48,4573.64 h60
  text "OTHER +/-" at 12430.46,4417.64 h60
  text "BOW & TWIST:" at 11404.23,4260.64 h60
  text "X" at 12243.53,4260.64 h60
  text "ANSI IPC-6012 TYPE 3 CLASS 2" at 12430.48,4260.64 h60
  text "OTHER +/-" at 12430.46,4102.13 h60
  text "DRILLING:" at 11329.46,3963.64 h60
  text "REFERENCE:" at 11404.23,3846.64 h60
  text "X" at 12052.46,3846.64 h60
  text "AS SHOWN" at 12239.46,3846.64 h60
  text "X" at 12953.46,3846.64 h60
  text "NC_DRILL FILES" at 13090.46,3846.64 h60
  text "PTH COPPER THICKNESS:" at 11404.23,3688.64 h60
  text "X" at 12534.46,3688.64 h60
  text "20-30 um" at 12671.46,3688.64 h60
  text "OTHER" at 13388.46,3688.64 h60
  text "BOARD FINISH:" at 11329.46,3529.64 h60
  text "SILKSCREEN:" at 11484.68,3411.64 h60
  text "X" at 12433.46,3411.64 h60
  text "TOP" at 12559.46,3411.64 h60
  text "X" at 12943.46,3411.64 h60
  text "BOTTOM" at 13070.46,3411.64 h60
  text "SILKSCREEN COLOR:" at 11484.68,3244.64 h60
  text "X" at 12432.42,3244.64 h60
  text "WHITE" at 12559.46,3244.64 h60
  text "OTHER" at 13070.46,3244.64 h60
  text "GREEN" at 12690.46,3085.44 h60
  text "X" at 13155,3085 h60
  text "OTHER" at 13308.46,3085.44 h60
  text "RED" at 13675,3085 h60
  text "SOLDER RESIST COLOR:" at 11484.68,3074.64 h60
  text "MATTE" at 12690.46,2915.44 h60
  text "X" at 13155,2915 h60
  text "SEMI-GLOSS" at 13308,2914.8 h60
  text "IMMERSION GOLD (ENIG)" at 12390.46,2726.92 h60
  text "ENEPIG" at 13728,2723.64 h60
  text "SURFACE FINISH:" at 11329.46,2722.64 h60
  text "X" at 12203.51,2717.64 h60
  text "IMM. TIN/SILVER OR EQUIV" at 11659,2565.64 h60
  text "OTHER" at 13090.46,2565.64 h60
  text "ARRAY/PANEL:" at 11329.46,2386.64 h60
  text "CUT AND TRIM PER M1 BOARD OUTLINE" at 12390.46,2382.35 h60
  text "N.C. ROUTE" at 12390.46,2230.64 h60
  text "X" at 13069.46,2230.64 h60
  text "V. SCORE" at 13256.46,2230.64 h60
  text "CERTIFICATION:" at 11329.46,2093.64 h60
  text "MATERIALS AND WORKMANSHIP FOR ALL PCBS" at 12054.46,2093.64 h60
  text "TO MEET OR EXCEED THE REQUIREMENTS OF:" at 12054.46,1995.64 h60
  text "X" at 11680.96,1859.13 h60
  text "ANSI IPC-A-600F CLASS ->" at 11819.96,1859.13 h60
  text "X" at 13459.02,1859.13 h60
  text "2" at 13577.96,1859.14 h60
  text "1" at 13262.96,1857.64 h60
  text "3" at 13931.96,1857.64 h60
  text "X" at 12495.02,1699.64 h60
  text "RoHS" at 12631.96,1699.64 h60
  text "OTHER" at 13276.36,1699.64 h60
  text "PER ORDER" at 13673.42,1699.64 h60
  text "ALL BOARDS MUST MEET OR EXCEED UL94-V0 REQUIREMENTS." at 11357,1534 h60
  text "PCB MUST BEAR THE UL94V-0 UL REGISTERED MATERIAL ID NUMBER" at 11357,1414 h60
  text "ADDITIONAL REQUIREMENTS:" at 11329.46,1240.64 h60
  text "MICROSECTION:" at 11404.23,1125.64 h60
  text "YES" at 12309.96,1125.64 h60
  text "REQUIRED" at 13171.46,969.49 h60
  text "BARE BOARD ELEC. TEST:" at 11404.23,966.64 h60
  text "NONE" at 12709.96,966.64 h60
  text "X" at 13634.46,966.64 h60
  text "PER ORDER" at 13763.46,966.64 h60
  text ".Layer_Name" at 577,-858.49 h60
M11 Gerber Information:
  lines w10: -292,-930.17 6308,-930.17 ; -292,-726.83 6310,-726.83 ; -292,-523.5 -292,-1133.5 3713,-1133.5 6310,-1133.5 6310,-523.5 -291.5,-523.5 -291.5,-1133.5 1284,-1133.5 ; 2173,-1133.5 2173,-523.5 ; 3440,-726.83 3440,-523.5 ; 4280,-726.83 4280,-523.5 ; 4902,-1140 4902,-937.17
  text "ALL ARTWORK VIEWED FROM TOP SIDE" at -228.5,-655.67 h60
  text "BOARD #:" at 2248,-655.67 h60
  text ".PRJ_Number" at 2793.5,-655.67 h60
  text "REV:" at 3638,-655.67 h60
  text ".PCB_Rev" at 3929.5,-655.67 h60
  text "SVN REV:" at 4476,-655.67 h60
  text ".VersionControl_RevNumber" at 4982,-655.67 h60
  text "LAYER NAME =" at -228.5,-858.49 h60
  text "TID #:" at 2248,-859 h60
  text ".TID" at 2793.5,-859 h60
  text "PLOT NAME =" at -228.5,-1064.34 h60
  text ".plot_File_Name" at 577,-1064.34 h60
  text "GENERATED    :" at 2250,-1064.34 h60
  text ".Print_Date" at 3119.5,-1064.34 h60
  text ".Print_Time" at 3848.5,-1064.34 h60
  text "TEXAS INSTRUMENTS" at 5113,-1064.34 h60
M12 Stackup:
  drawing of 191 lines, arcs and shapes, not listed
  text "Layer" at 9790.34,7830 h60
  text "Name" at 10200.26,7830 h60
  text "Material" at 11130,7830 h60
  text "Thickness" at 11989.77,7830 h60
  text "Constant" at 12639.6,7830 h60
  text "Board Layer Stack" at 13209.46,7830 h60
  text "1" at 9790.34,7710 h60
  text "Top Overlay" at 10200.26,7710 h60
  text "2" at 9790.34,7590 h60
  text "Top Solder" at 10200.26,7590 h60
  text "Solder Resist" at 11130,7590 h60
  text "0.40mil" at 11989.77,7590 h60
  text "3.5" at 12639.6,7590 h60
  text "3" at 9790.34,7470 h60
  text "Top Layer" at 10200.26,7470 h60
  text "Copper" at 11130,7470 h60
  text "1.40mil" at 11989.77,7470 h60
  text "4" at 9790.34,7350 h60
  text "Dielectric1" at 10200.26,7350 h60
  text "FR-4" at 11130,7350 h60
  text "59.20mil" at 11989.77,7350 h60
  text "4.8" at 12639.6,7350 h60
  text "5" at 9790.34,7230 h60
  text "Bottom Layer" at 10200.26,7230 h60
  text "Copper" at 11130,7230 h60
  text "1.40mil" at 11989.77,7230 h60
  text "6" at 9790.34,7110 h60
  text "Bottom Solder" at 10200.26,7110 h60
  text "Solder Resist" at 11130,7110 h60
  text "0.40mil" at 11989.77,7110 h60
  text "3.5" at 12639.6,7110 h60
  text "7" at 9790.34,6990 h60
  text "Bottom Overlay" at 10200.26,6990 h60
  text ".Layer_Name" at 577,-858.49 h60
M13 Component Bodies Top:
  text ".Layer_Name" at 577,-858.49 h60
M14 Component Bodies Bottom:
  text ".Layer_Name" at 577,-858.49 h60
M15 Courtyards Top:
  text ".Layer_Name" at 577,-858.49 h60
M16 Courtyards Bottom:
  text ".Layer_Name" at 577,-858.49 h60
Drill Drawing:
  circle w10: c6013.58,7487.81 r22.02
  lines w10: 5991.56,6970.31 5991.56,6981.32 6002.57,6992.33 5991.56,7003.34 5991.56,7014.35 6002.57,7014.35 6013.58,7003.34 6024.59,7014.35 6035.6,7014.35 6035.6,7003.34 6024.59,6992.33 6035.6,6981.32 6035.6,6970.31 6024.59,6970.31 6013.58,6981.32 6002.57,6970.31 5991.56,6970.31 ; 5991.56,7069.41 6035.6,7069.41 6035.6,7113.45 5991.56,7113.45 5991.56,7069.41 ; 5991.56,7212.55 6035.6,7212.55 6013.58,7168.5 5991.56,7212.55 ; 5991.56,7267.6 6035.6,7267.6 6035.6,7311.64 5991.56,7311.64 5991.56,7267.6 ; 5991.56,7377.71 6002.57,7377.71 6013.58,7366.7 6024.59,7377.71 6035.6,7377.71 6024.59,7388.72 6035.6,7399.73 6024.59,7399.73 6013.58,7410.74 6002.57,7399.73 5991.56,7399.73 6002.57,7388.72 5991.56,7377.71 ; 5991.56,7564.89 6013.58,7575.9 6035.6,7564.89 6024.59,7586.91 6035.6,7608.93 6013.58,7597.92 5991.56,7608.93 6002.57,7586.91 5991.56,7564.89 ; 5991.56,7675 6002.57,7675 6002.57,7663.99 6024.59,7663.99 6024.59,7675 6035.6,7675 6035.6,7697.02 6024.59,7697.02 6024.59,7708.03 6002.57,7708.03 6002.57,7697.02 5991.56,7697.02 5991.56,7675 ; 5991.56,7785.1 6013.58,7763.08 6035.6,7785.1 6013.58,7807.13 5991.56,7785.1 ; 6000.37,7078.22 6026.8,7078.22 6026.8,7104.64 6000.37,7104.64 6000.37,7078.22
  lines w12: 5951,6940.58 9604.95,6940.58 ; 5951,7832.45 9604.95,7832.45 ; 6265.93,6841.48 6265.93,7931.55 ; 6582.66,6841.48 6582.66,7931.55 ; 7203.56,6841.48 7203.56,7931.55 ; 7447.4,6841.48 7447.4,7931.55 ; 7807.19,6841.48 7807.19,7931.55 ; 8514.77,6841.48 8514.77,7931.55 ; 9028.41,6841.48 9028.41,7931.55 ; 5951,6841.48 9604.95,6841.48 9604.95,7931.55 5951,7931.55 5951,6841.48
  text "Symbol" at 6010.46,7862.18 h72
  text "Quantity" at 6295.66,7862.18 h72
  text "Finished Hole Size" at 6612.39,7862.18 h72
  text "Plated" at 7233.29,7862.18 h72
  text "Hole Type" at 7477.13,7862.18 h72
  text "Drill Layer Pair" at 7836.92,7862.18 h72
  text "Hole Tolerance" at 8544.5,7862.18 h72
  text "Hole Length" at 9058.14,7862.18 h72
  text "6" at 6295.66,7763.08 h60
  text "35.43mil (0.900mm)" at 6612.39,7763.08 h60
  text "NPTH" at 7233.29,7763.08 h60
  text "Round" at 7477.13,7763.08 h60
  text "Top Layer - Bottom Layer" at 7836.92,7763.08 h60
  text "-" at 9058.14,7763.08 h60
  text "4" at 6295.66,7663.99 h60
  text "125.00mil (3.175mm)" at 6612.39,7663.99 h60
  text "NPTH" at 7233.29,7663.99 h60
  text "Round" at 7477.13,7663.99 h60
  text "Top Layer - Bottom Layer" at 7836.92,7663.99 h60
  text "-" at 9058.14,7663.99 h60
  text "3" at 6295.66,7564.89 h60
  text "7.87mil (0.200mm)" at 6612.39,7564.89 h60
  text "PTH" at 7233.29,7564.89 h60
  text "Round" at 7477.13,7564.89 h60
  text "Top Layer - Bottom Layer" at 7836.92,7564.89 h60
  text "-" at 9058.14,7564.89 h60
  text "304" at 6295.66,7465.79 h60
  text "12.00mil (0.305mm)" at 6612.39,7465.79 h60
  text "PTH" at 7233.29,7465.79 h60
  text "Round" at 7477.13,7465.79 h60
  text "Top Layer - Bottom Layer" at 7836.92,7465.79 h60
  text "-" at 9058.14,7465.79 h60
  text "3" at 6295.66,7366.7 h60
  text "16.00mil (0.406mm)" at 6612.39,7366.7 h60
  text "PTH" at 7233.29,7366.7 h60
  text "Round" at 7477.13,7366.7 h60
  text "Top Layer - Bottom Layer" at 7836.92,7366.7 h60
  text "-" at 9058.14,7366.7 h60
  text "36" at 6295.66,7267.6 h60
  text "40.00mil (1.016mm)" at 6612.39,7267.6 h60
  text "PTH" at 7233.29,7267.6 h60
  text "Round" at 7477.13,7267.6 h60
  text "Top Layer - Bottom Layer" at 7836.92,7267.6 h60
  text "-" at 9058.14,7267.6 h60
  text "22" at 6295.66,7168.5 h60
  text "40.16mil (1.020mm)" at 6612.39,7168.5 h60
  text "PTH" at 7233.29,7168.5 h60
  text "Round" at 7477.13,7168.5 h60
  text "Top Layer - Bottom Layer" at 7836.92,7168.5 h60
  text "-" at 9058.14,7168.5 h60
  text "2" at 6295.66,7069.41 h60
  text "19.69mil (0.500mm)" at 6612.39,7069.41 h60
  text "PTH" at 7233.29,7069.41 h60
  text "Slot" at 7477.13,7069.41 h60
  text "Top Layer - Bottom Layer" at 7836.92,7069.41 h60
  text "43.31mil (1.100mm)" at 9058.14,7069.41 h60
  text "2" at 6295.66,6970.31 h60
  text "23.62mil (0.600mm)" at 6612.39,6970.31 h60
  text "PTH" at 7233.29,6970.31 h60
  text "Slot" at 7477.13,6970.31 h60
  text "Top Layer - Bottom Layer" at 7836.92,6970.31 h60
  text "51.18mil (1.300mm)" at 9058.14,6970.31 h60
  text "382 Total" at 6295.66,6871.21 h60
  text "Slot definitions :" at 6010.46,6791.87 h60
  text "Routed Path Length" at 6452.42,6791.87 h60
  text "= Calculated from tool start centre position to tool end centre position." at 6983.3,6791.87 h60
  text "Hole Length" at 6452.42,6742.26 h60
  text "= Routed Path Length + Tool Size = Slot length as defined in the PCB layout" at 6783.99,6742.26 h60
  text ".Layer_Name" at 577,-858.49 h60
M17 Embedded Cavity:
  text ".Layer_Name" at 577,-858.49 h60
M18 Embedded Assembly:
  text ".Layer_Name" at 577,-858.49 h60
M19 Embedded Keepout:
  text ".Layer_Name" at 577,-858.49 h60

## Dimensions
50,1400 to 50,4300 on M2 Board Dimensions
50,1400 to 2350,1400 on M2 Board Dimensions
0,-400 to 1000,-400 on M2 Board Dimensions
